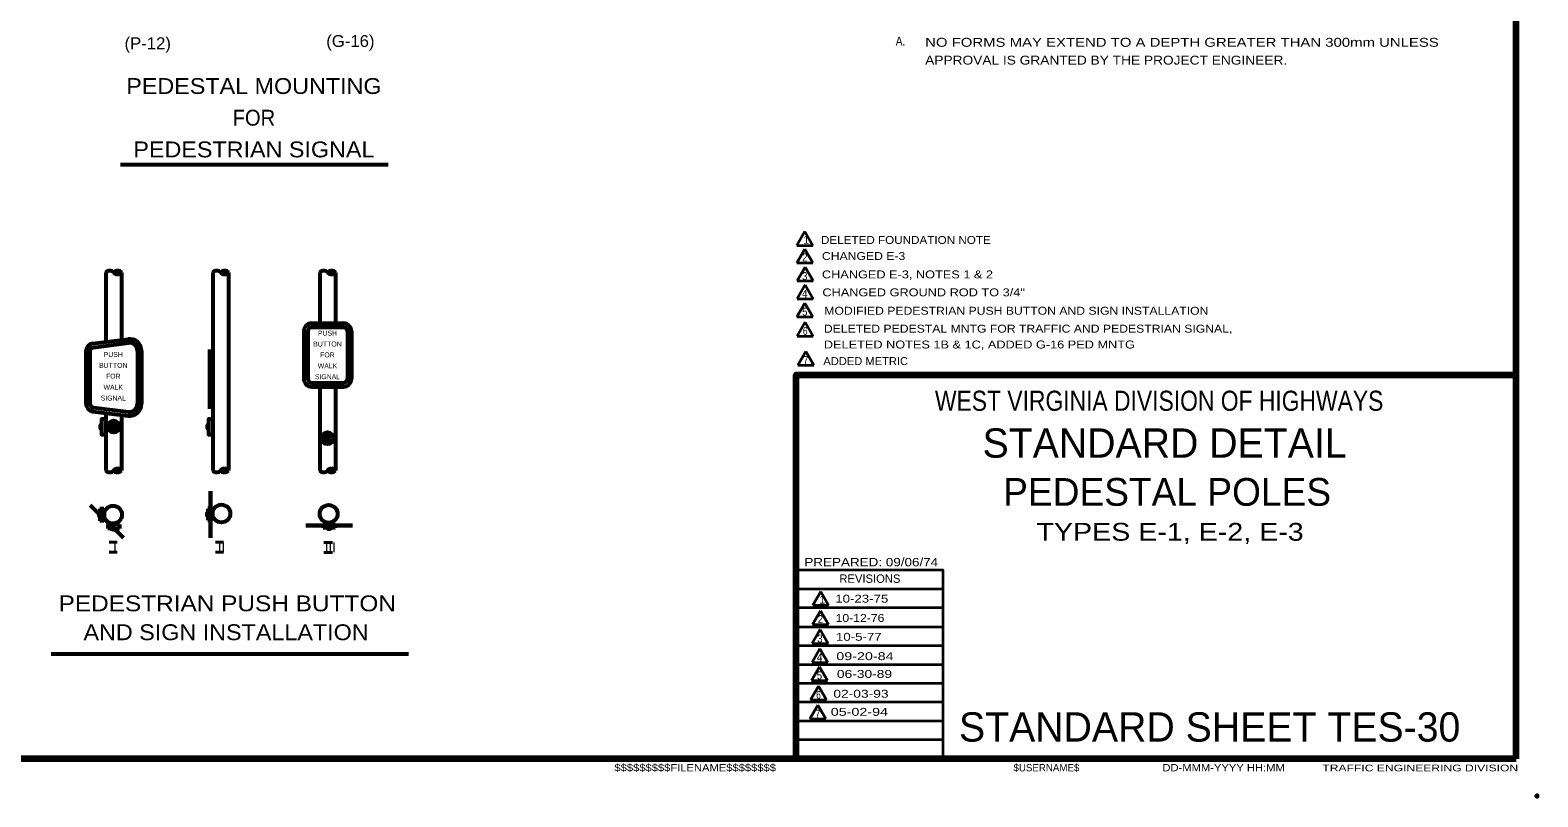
# Model space of a CAD drawing. Extents: x -761 to 95, y 34 to 578.
# Drawn here: x -361.7 to 94.7, y 34.3 to 266.6 of the extents above; entities that cross this region are included whole.
import ezdxf
from ezdxf.enums import TextEntityAlignment as Align

# ---------------------------------------------------------------- set-up
doc = ezdxf.new("R2010")
doc.units = 0
doc.header["$LTSCALE"] = 0.96
doc.header["$PDMODE"] = 32
doc.header["$PDSIZE"] = 0.48
doc.layers.add('1', color=7, linetype='Continuous', lineweight=53)
doc.layers.add('61', color=7, linetype='Continuous', lineweight=35)

msp = doc.modelspace()

# ---------------------------------------------------------------- linework, layer by layer
at = {"layer": '1', "lineweight": 158}
for q in [(88.1275, 571.9431), (88.1275, 162.1431), (-703.4725, 45.8431)]:
    msp.add_line((88.1275, 45.8431), q, dxfattribs=at)
at = {"layer": '1', "lineweight": 13}
msp.add_line((88.1275, 45.8431), (88.1275, 571.9431), dxfattribs=at)
at = {"layer": '1'}
for p, q in [((-334.4273, 225.8275), (-253.3466, 225.8275)), ((-338.8613, 193.1345), (-338.8613, 172.1345)), ((-334.0613, 193.1345), (-334.0613, 172.7345)), ((-301.6613, 193.1345), (-301.6613, 172.7345)), ((-274.0613, 193.1345), (-274.0613, 177.8067)), ((-269.2613, 193.1345), (-269.2613, 177.7431)), ((-278.9122, 175.3431), (-278.9122, 160.9431)), ((-277.7122, 175.3431), (-277.7122, 160.9431)), ((-276.5122, 177.7431), (-266.9122, 177.7431)), ((-276.5122, 176.5431), (-266.9122, 176.5431)), ((-265.7122, 175.3431), (-265.7122, 160.9431)), ((-264.5122, 175.3431), (-264.5122, 160.9431)), ((-344.8613, 169.2658), (-344.8613, 153.4637)), ((-343.6613, 169.2659), (-343.6613, 153.4636)), ((-342.759, 171.6473), (-332.1078, 172.9787)), ((-342.6101, 170.4566), (-331.959, 171.788)), ((-329.2613, 169.4065), (-329.2613, 153.323)), ((-328.0613, 169.4065), (-328.0613, 153.323)), ((-307.3613, 151.795), (-307.3613, 169.795)), ((-301.6613, 172.7345), (-301.6613, 133.195)), ((-307.3613, 166.915), (-306.4613, 166.915)), ((-307.3613, 165.595), (-306.4613, 165.595)), ((-307.3613, 155.995), (-306.4613, 155.995)), ((-276.5122, 159.7431), (-266.9122, 159.7431)), ((-276.5122, 158.5431), (-266.9122, 158.5431)), ((-274.0613, 158.5431), (-274.0613, 133.195)), ((-269.2613, 158.5431), (-269.2613, 133.195)), ((-342.759, 151.0822), (-332.1078, 149.7508)), ((-342.6101, 152.2729), (-331.959, 150.9415)), ((-307.3613, 154.675), (-306.4613, 154.675)), ((-338.8613, 150.595), (-338.8613, 133.195)), ((-334.0613, 149.995), (-334.0613, 133.195)), ((-339.4609, 121.5041), (-340.6609, 121.5041)), ((-339.3409, 119.7041), (-340.5409, 119.7041)), ((-306.7164, 121.619), (-307.9164, 121.619)), ((-306.5964, 119.819), (-307.7964, 119.819)), ((-339.4609, 117.9041), (-340.6609, 117.9041)), ((-338.2769, 116.7786), (-338.2769, 115.5786)), ((-336.4769, 116.8987), (-336.4769, 115.6986)), ((-334.6769, 116.7786), (-334.6769, 115.5786)), ((-306.7164, 118.019), (-307.9164, 118.019)), ((-273.0175, 117.0084), (-273.0175, 115.8084)), ((-271.2175, 117.1285), (-271.2175, 115.9284)), ((-269.4175, 117.0084), (-269.4175, 115.8084)), ((-355.3899, 77.6007), (-247.1738, 77.6007))]:
    msp.add_line(p, q, dxfattribs=at)
at = {"layer": '1', "lineweight": 35}
for p, q in [((-127.2414, 205.5194), (-129.6414, 201.3625)), ((-127.2414, 205.5194), (-124.8414, 201.3625)), ((-129.6414, 201.3625), (-124.8414, 201.3625)), ((-127.2414, 200.2208), (-129.6414, 196.0639)), ((-127.2414, 200.2208), (-124.8414, 196.0639)), ((-129.6414, 196.0639), (-124.8414, 196.0639)), ((-127.1531, 194.7456), (-129.5531, 190.5887)), ((-127.1531, 194.7456), (-124.7531, 190.5887)), ((-129.5531, 190.5887), (-124.7531, 190.5887)), ((-127.1531, 189.3587), (-129.5531, 185.2018)), ((-127.1531, 189.3587), (-124.7531, 185.2018)), ((-127.2414, 183.8834), (-129.6414, 179.7265)), ((-129.5531, 185.2018), (-124.7531, 185.2018)), ((-127.2414, 183.8834), (-124.8414, 179.7265)), ((-129.6414, 179.7265), (-124.8414, 179.7265)), ((-127.1088, 178.0469), (-129.5088, 173.89)), ((-127.1088, 178.0469), (-124.7088, 173.89)), ((-129.5088, 173.89), (-124.7088, 173.89)), ((-126.9393, 169.2319), (-129.3393, 165.075)), ((-126.9393, 169.2319), (-124.5393, 165.075)), ((-129.3393, 165.075), (-124.5393, 165.075)), ((-85.3725, 97.2431), (-129.8725, 97.2431)), ((-122.4308, 96.505), (-124.8308, 92.3481)), ((-122.4308, 96.505), (-120.0308, 92.3481)), ((-85.3725, 91.5431), (-129.8725, 91.5431)), ((-124.8308, 92.3481), (-120.0308, 92.3481)), ((-122.5086, 90.6617), (-124.9086, 86.5048)), ((-122.5086, 90.6617), (-120.1086, 86.5048)), ((-85.3725, 85.7431), (-129.8725, 85.7431)), ((-122.5759, 84.9531), (-124.9759, 80.7962)), ((-124.9086, 86.5048), (-120.1086, 86.5048)), ((-122.5759, 84.9531), (-120.1759, 80.7962)), ((-85.3725, 80.0431), (-129.8725, 80.0431)), ((-122.6537, 79.1772), (-125.0537, 75.0203)), ((-124.9759, 80.7962), (-120.1759, 80.7962)), ((-122.6537, 79.1772), (-120.2537, 75.0203)), ((-85.3725, 74.3431), (-129.8725, 74.3431)), ((-122.8197, 73.7018), (-125.2197, 69.5449)), ((-125.0537, 75.0203), (-120.2537, 75.0203)), ((-122.8197, 73.7018), (-120.4197, 69.5449)), ((-85.3725, 68.6431), (-129.8725, 68.6431)), ((-125.2197, 69.5449), (-120.4197, 69.5449)), ((-123.0908, 67.8471), (-125.4908, 63.6902)), ((-123.0908, 67.8471), (-120.6908, 63.6902)), ((-85.3725, 62.9431), (-129.8725, 62.9431)), ((-123.3171, 62.1043), (-125.7171, 57.9474)), ((-125.4908, 63.6902), (-120.6908, 63.6902)), ((-123.3171, 62.1043), (-120.9171, 57.9474)), ((-85.3725, 57.2431), (-129.8725, 57.2431)), ((-125.7171, 57.9474), (-120.9171, 57.9474)), ((-85.3725, 51.5431), (-129.8725, 51.5431))]:
    msp.add_line(p, q, dxfattribs=at)
at = {"layer": '1', "lineweight": 60}
for p, q in [((-307.1764, 126.8922), (-307.1764, 112.7575)), ((-343.5322, 122.6523), (-333.4856, 112.7504)), ((-278.3298, 116.5307), (-264.1951, 116.5306))]:
    msp.add_line(p, q, dxfattribs=at)
at = {"layer": '1', "lineweight": 40}
for p, q in [((-337.7963, 111.4509), (-335.3963, 111.4509)), ((-305.6334, 111.4283), (-303.2334, 111.4283)), ((-272.8696, 111.372), (-270.2296, 111.372)), ((-337.7963, 108.4509), (-335.3963, 108.4509)), ((-305.6334, 108.4283), (-303.2334, 108.4283)), ((-272.8696, 108.372), (-270.2296, 108.372))]:
    msp.add_line(p, q, dxfattribs=at)
at = {"layer": '1'}
for points in [[(-306.4613, 193.1345), (-306.4613, 172.1345), (-306.4613, 133.195)], [(-338.8613, 143.995), (-340.0613, 143.995), (-340.0613, 148.795), (-338.8613, 148.795)], [(-306.4613, 143.995), (-307.6613, 143.995), (-307.6613, 148.795), (-306.4613, 148.795)], [(-340.6609, 121.5041), (-340.5409, 119.7041), (-340.6609, 117.9041)], [(-339.4609, 121.5041), (-339.3409, 119.7041), (-339.4609, 117.9041)], [(-307.9164, 121.619), (-307.7964, 119.819), (-307.9164, 118.019)], [(-306.7164, 121.619), (-306.5964, 119.819), (-306.7164, 118.019)], [(-338.2769, 116.7786), (-336.4769, 116.8987), (-334.6769, 116.7786)], [(-338.2769, 115.5786), (-336.4769, 115.6986), (-334.6769, 115.5786)], [(-273.0175, 117.0084), (-271.2175, 117.1285), (-269.4175, 117.0084)], [(-273.0175, 115.8084), (-271.2175, 115.9284), (-269.4175, 115.8084)]]:
    msp.add_lwpolyline(points, dxfattribs=at)
at = {"layer": '1', "lineweight": 158}
msp.add_lwpolyline([(-129.8725, 45.8431), (-129.8725, 162.1431), (88.1275, 162.1431)], dxfattribs=at)
at = {"layer": '1', "lineweight": 35}
msp.add_lwpolyline([(-85.3725, 45.8431), (-85.3725, 102.9431), (-129.8725, 102.9431)], dxfattribs=at)
at = {"layer": '1'}
for centre, radius in [((-336.4698, 146.4775), 1.8), ((-336.4698, 146.4775), 0.9), ((-336.4698, 146.4775), 0.3), ((-336.4797, 146.4783), 0.2517), ((-336.4876, 146.4822), 0.1968), ((-336.4916, 146.4822), 0.1533), ((-336.4954, 146.4901), 0.1101), ((-336.5033, 146.498), 0.0634), ((-336.5033, 146.498), 0.0236), ((-271.7122, 142.9431), 1.8), ((-271.7122, 142.9431), 0.9), ((-271.7122, 142.9431), 0.3), ((-271.7221, 142.9439), 0.2517), ((-271.73, 142.9479), 0.1968), ((-271.7339, 142.9478), 0.1533), ((-271.7378, 142.9557), 0.1101), ((-271.7457, 142.9635), 0.0634), ((-271.7457, 142.9636), 0.0236), ((-336.6522, 119.7871), 2.7), ((-303.8497, 120.1174), 2.7), ((-271.3928, 120.0169), 2.7)]:
    msp.add_circle(centre, radius, dxfattribs=at)
for centre, radius, start, end in [((-337.6613, 192.0354), 1.6273, 42.48748, 137.51252), ((-335.2849, 194.2744), 1.6273, 222.48748, 317.51252), ((-335.2741, 192.055), 1.6273, 42.48748, 137.51252), ((-305.2613, 192.0354), 1.6273, 42.48748, 137.51252), ((-302.8849, 194.2744), 1.6273, 222.48748, 317.51252), ((-302.8741, 192.055), 1.6273, 42.48748, 137.51252), ((-272.8613, 192.0354), 1.6273, 42.48748, 137.51252), ((-270.4849, 194.2744), 1.6273, 222.48748, 317.51252), ((-270.4741, 192.055), 1.6273, 42.48748, 137.51252), ((-276.5122, 175.3431), 2.4, 90, 180), ((-276.5122, 175.3431), 1.2, 90, 180), ((-266.9122, 175.3431), 2.4, 0, 90), ((-266.9122, 175.3431), 1.2, 0, 90), ((-342.4613, 169.2658), 2.4, 97.12478, 180), ((-342.4613, 169.2659), 1.2, 97.12502, 180), ((-331.6613, 169.4065), 3.6, 0, 97.12484), ((-331.6613, 169.4065), 2.4, 0, 97.12508), ((-276.5122, 160.9431), 2.4, 180, 270), ((-276.5122, 160.9431), 1.2, 180, 270), ((-266.9122, 160.9431), 2.4, 270, 0), ((-266.9122, 160.9431), 1.2, 270, 0), ((-342.4613, 153.4637), 2.4, 180, 262.87522), ((-342.4613, 153.4636), 1.2, 180, 262.87498), ((-331.6613, 153.323), 3.6, 262.87516, 0), ((-331.6613, 153.323), 2.4, 262.87492, 0), ((-339.535, 146.395), 1.0426, 120.31709, 239.68291), ((-307.135, 146.395), 1.0426, 120.31709, 239.68291), ((-337.6613, 134.2941), 1.6273, 222.48748, 317.51252), ((-335.3303, 134.2521), 1.6273, 222.48748, 317.51252), ((-335.3074, 132.1), 1.6273, 42.48748, 137.51252), ((-305.2613, 134.2941), 1.6273, 222.48748, 317.51252), ((-302.9303, 134.2521), 1.6273, 222.48748, 317.51252), ((-302.9074, 132.1), 1.6273, 42.48748, 137.51252), ((-272.8613, 134.2941), 1.6273, 222.48748, 317.51252), ((-270.5303, 134.2521), 1.6273, 222.48748, 317.51252), ((-270.5074, 132.1), 1.6273, 42.48748, 137.51252), ((-339.783, 119.7041), 1.2161, 132.26342, 227.73658), ((-307.0385, 119.819), 1.2161, 132.26342, 227.73658), ((-336.4769, 116.4565), 1.2161, 222.26342, 317.73658), ((-271.2175, 116.6863), 1.2161, 222.26342, 317.73658)]:
    msp.add_arc(centre, radius, start, end, dxfattribs=at)
msp.add_point((94.4275, 34.5431), dxfattribs=at)
at = {"layer": '61', "lineweight": 53}
for q in [(-64.5725, 45.8431), (-64.5725, 45.8431), (-64.5725, 45.8431), (-64.2725, 45.8431), (-64.2725, 45.8431)]:
    msp.add_line((88.1275, 45.8431), q, dxfattribs=at)

# ---------------------------------------------------------------- texts
at = {"layer": '1'}
for s, height, width, p in [('(G-16)', 3.6, 1.05, (-264.8079, 261.4543)), ('(P-12)', 3.6, 1.05, (-326.1576, 260.7887)), ('PEDESTAL MOUNTING', 4.8, 1.1, (-294.0074, 247.2226)), ('FOR', 4.8, 0.95, (-294.0073, 237.6226)), ('PEDESTRIAN SIGNAL', 4.8, 1.1, (-294.0073, 228.0226)), ('2', 2.4, 0.9, (-127.2459, 196.4995)), ('3', 2.4, 0.9, (-127.2459, 190.8476)), ('4', 2.4, 0.95, (-127.2459, 185.549)), ('5', 2.4, 0.9, (-127.2459, 180.0738)), ('6', 2.4, 0.8, (-127.1133, 174.2373)), ('BUTTON', 1.5, 1.05, (-271.7459, 170.7278)), ('FOR', 1.5, 0.95, (-271.7459, 167.4278)), ('BUTTON', 1.5, 1.05, (-336.5861, 164.2535)), ('7', 2.4, 0.9, (-126.9345, 165.4223)), ('FOR', 1.5, 0.95, (-336.5861, 160.9535)), ('WEST VIRGINIA DIVISION OF HIGHWAYS', 6.089, 0.85, (-19.9725, 151.2431)), ('TYPES E-1, E-2, E-3', 5.4, 1.2, (-16.6659, 111.8952)), ('PEDESTRIAN PUSH BUTTON', 4.8, 1.15, (-302.0826, 90.5173)), ('2', 2.4, 0.9, (-122.5131, 86.9404)), ('AND SIGN INSTALLATION', 4.8, 1.1, (-302.4429, 81.7681)), ('3', 2.4, 0.9, (-122.6687, 81.0551)), ('4', 2.4, 0.95, (-122.7465, 75.3675)), ('5', 2.4, 0.9, (-122.8242, 69.8922)), ('6', 2.4, 0.8, (-123.0953, 64.0375)), ('02-03-93', 2.4, 1.3, (-110.2418, 64.3407)), ('7', 2.4, 0.9, (-123.3123, 58.2947)), ('05-02-94', 2.4, 1.35, (-110.7128, 58.8523))]:
    msp.add_text(s, height=height, dxfattribs=dict(at, width=width)).set_placement(p, align=Align.CENTER)
for s, height, width, p in [('A.', 2.7, 0.85, (-99.7098, 261.8996)), ('NO FORMS MAY EXTEND TO A DEPTH GREATER THAN 300mm UNLESS', 2.7, 1.25, (-90.8037, 261.5124)), ('APPROVAL IS GRANTED BY THE PROJECT ENGINEER.', 2.7, 1.15, (-90.8037, 256.1124)), ('DELETED FOUNDATION NOTE', 2.4, 1.1, (-122.3394, 201.7885)), ('CHANGED E-3', 2.4, 1.15, (-122.0536, 196.9291)), ('CHANGED E-3, NOTES 1 & 2', 2.4, 1.2, (-122.0535, 191.3551)), ('CHANGED GROUND ROD TO 3/4"', 2.4, 1.2, (-121.9107, 185.924)), ('MODIFIED PEDESTRIAN PUSH BUTTON AND SIGN INSTALLATION', 2.4, 1.15, (-121.3389, 180.35)), ('DELETED PEDESTAL MNTG FOR TRAFFIC AND PEDESTRIAN SIGNAL,', 2.4, 1.15, (-121.4715, 174.9239)), ('DELETED NOTES 1B & 1C, ADDED G-16 PED MNTG', 2.4, 1.2, (-121.4715, 170.1239)), ('ADDED METRIC', 2.4, 1.05, (-121.6345, 165.0968)), ('PREPARED: 09/06/74', 2.537, 1.2, (-127.3725, 104.1431)), ('10-23-75', 2.4, 1.25, (-118.0198, 93.1369)), ('10-12-76', 2.4, 1.15, (-117.9209, 87.2936)), ('10-5-77', 2.4, 1.25, (-117.8116, 81.585)), ('09-20-84', 2.4, 1.35, (-117.7128, 75.7208)), ('06-30-89', 2.4, 1.3, (-117.5256, 70.3338)), ('$$$$$$$$$FILENAME$$$$$$$$', 2.2, 1.15, (-184.8725, 42.0431)), ('DD-MMM-YYYY HH:MM', 2.2, 1.15, (-18.9725, 42.0431)), ('TRAFFIC ENGINEERING DIVISION', 2.031, 1.35, (29.4275, 42.0431))]:
    msp.add_text(s, height=height, dxfattribs=dict(at, width=width)).set_placement(p)
for s, height, p in [('1', 2.4, (-127.6874, 201.8344)), ('REVISIONS', 2.537, (-116.7725, 99.1431)), ('1', 2.4, (-122.8768, 92.82)), ('STANDARD SHEET TES-30', 8.881, (-80.5725, 51.0431)), ('$USERNAME$', 2.2, (-64.0725, 42.0431))]:
    msp.add_text(s, height=height, dxfattribs=at).set_placement(p)
for s, height, p in [('PUSH', 1.5, (-271.7459, 174.0278)), ('PUSH', 1.5, (-336.5861, 167.5535)), ('WALK', 1.5, (-271.7459, 164.1278)), ('SIGNAL', 1.5, (-271.7459, 160.8278)), ('SIGNAL', 1.5, (-336.5861, 154.3535)), ('WALK', 1.5, (-336.5861, 157.6535)), ('STANDARD DETAIL', 8.881, (-18.3225, 137.0431)), ('PEDESTAL POLES', 8.4, (-17.5593, 122.4766)), ('I', 3, (-336.0661, 108.462)), ('II', 3, (-303.8383, 108.3759)), ('III', 3, (-270.8983, 108.3761))]:
    msp.add_text(s, height=height, dxfattribs=at).set_placement(p, align=Align.CENTER)

doc.saveas('drawing.dxf')
